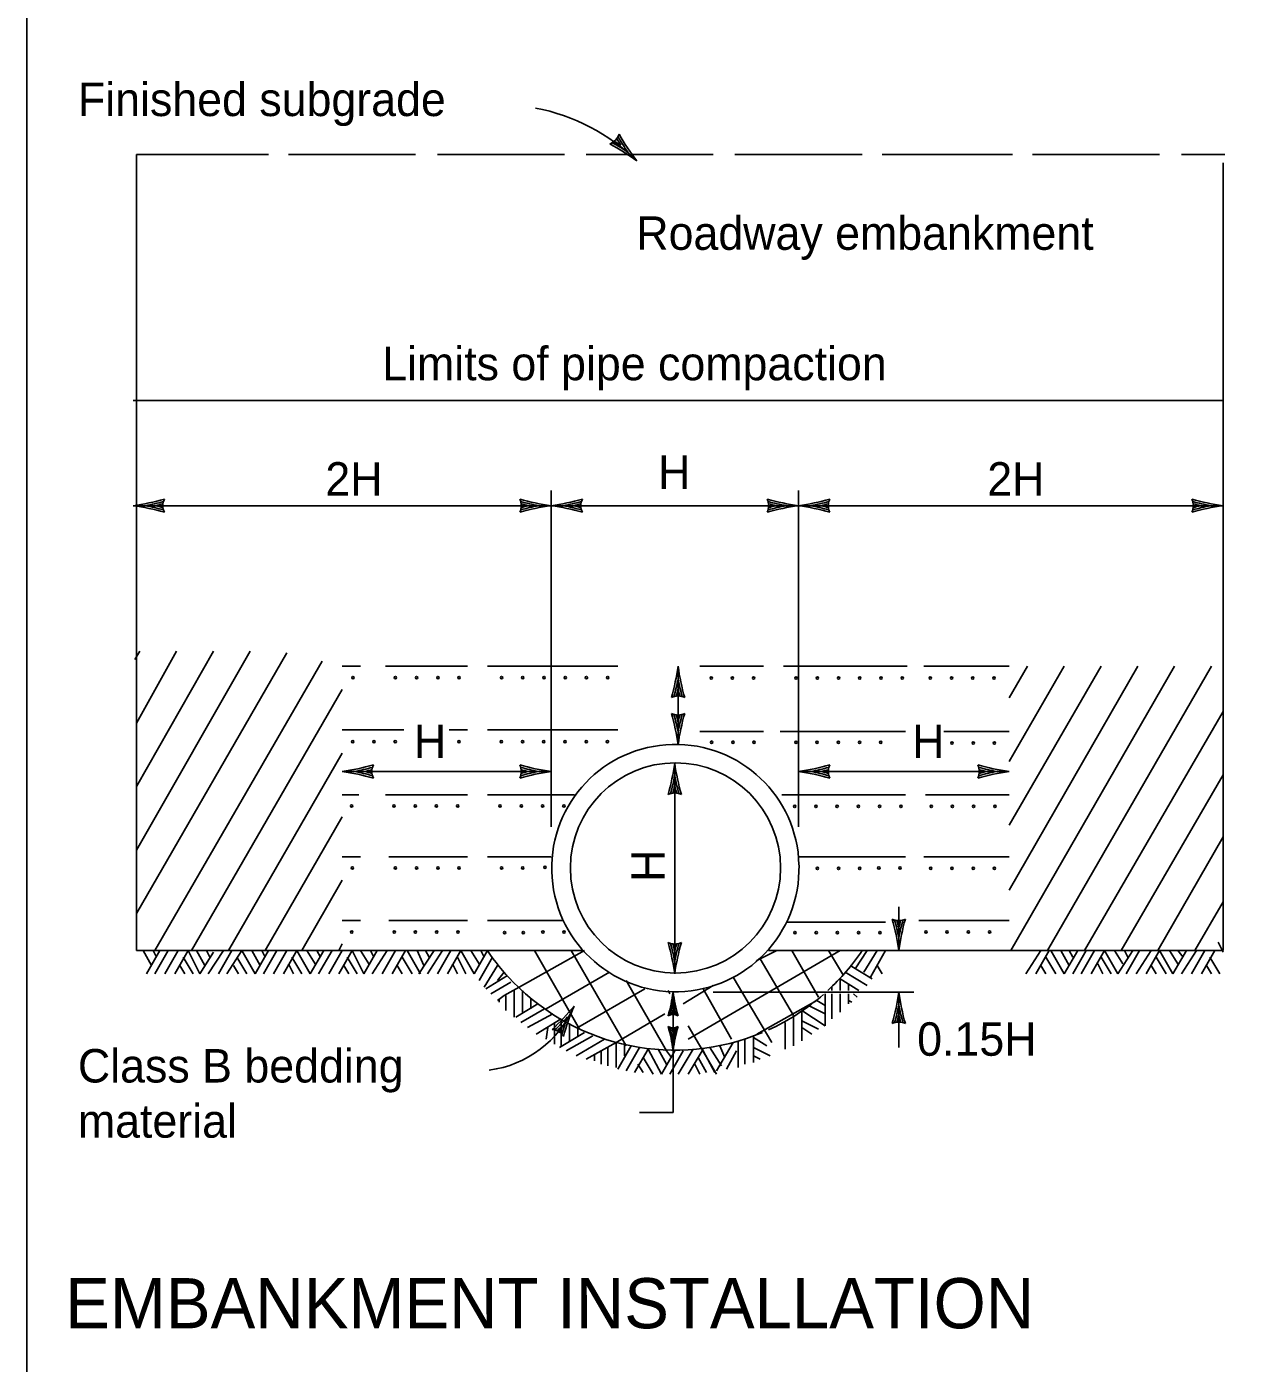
# Model space of a CAD drawing. Extents: x 0 to 390, y 0 to 265.
# Drawn here: x 0 to 73, y 105.1 to 185.1 of the extents above; entities that cross this region are included whole.
import ezdxf

# ---------------------------------------------------------------- set-up
doc = ezdxf.new("R2010")
doc.units = 0
doc.layers.add('D_Details', color=7, linetype='Continuous')
doc.layers.add('Default', color=7, linetype='Continuous')

msp = doc.modelspace()

# ---------------------------------------------------------------- linework, layer by layer
at = {"layer": 'D_Details'}
for p, q in [((6.562, 177.42), (14.462, 177.42)), ((6.562, 177.42), (6.562, 129.82)), ((15.662, 177.42), (23.262, 177.42)), ((24.562, 177.42), (32.162, 177.42)), ((33.462, 177.42), (41.062, 177.42)), ((42.362, 177.42), (49.962, 177.42)), ((51.162, 177.42), (58.962, 177.42)), ((60.162, 177.42), (67.762, 177.42)), ((69.062, 177.42), (71.662, 177.42)), ((71.562, 176.92), (71.562, 129.82)), ((6.362, 162.72), (71.562, 162.72)), ((31.362, 137.22), (31.362, 157.32)), ((46.162, 137.22), (46.162, 157.32)), ((6.362, 156.42), (31.362, 156.42)), ((31.362, 156.42), (46.162, 156.42)), ((46.162, 156.42), (71.562, 156.42)), ((6.462, 147.22), (6.762, 147.72)), ((6.562, 143.42), (8.962, 147.72)), ((6.562, 139.62), (11.162, 147.72)), ((6.562, 135.82), (13.362, 147.72)), ((6.562, 132.02), (15.562, 147.62)), ((7.662, 129.82), (17.662, 147.12)), ((18.862, 146.82), (19.962, 146.82)), ((21.462, 146.82), (26.362, 146.82)), ((27.562, 146.82), (35.362, 146.82)), ((38.962, 146.82), (38.962, 142.12)), ((40.262, 146.82), (44.062, 146.82)), ((45.262, 146.82), (52.662, 146.82)), ((53.662, 146.82), (58.762, 146.82)), ((58.762, 133.42), (66.462, 146.82)), ((58.762, 137.32), (64.262, 146.82)), ((58.762, 141.12), (62.062, 146.82)), ((58.762, 144.92), (59.862, 146.82)), ((58.862, 129.82), (68.662, 146.82)), ((61.062, 129.82), (70.862, 146.82)), ((9.862, 129.82), (18.862, 145.42)), ((63.262, 129.82), (71.562, 144.12)), ((18.862, 143.02), (22.562, 143.02)), ((25.262, 143.02), (26.362, 143.02)), ((27.562, 143.02), (35.362, 143.02)), ((40.262, 142.92), (44.062, 142.92)), ((45.062, 142.92), (52.562, 142.92)), ((54.862, 142.92), (58.762, 142.92)), ((12.062, 129.82), (18.862, 141.62)), ((38.762, 141.02), (38.762, 128.42)), ((18.862, 140.52), (31.362, 140.52)), ((46.162, 140.52), (58.762, 140.52)), ((65.462, 129.82), (71.562, 140.32)), ((18.862, 139.12), (19.862, 139.12)), ((21.462, 139.12), (26.362, 139.12)), ((27.562, 139.12), (32.762, 139.12)), ((45.162, 139.12), (52.562, 139.12)), ((53.762, 139.12), (58.762, 139.12)), ((14.262, 129.82), (18.862, 137.82)), ((67.662, 129.82), (71.562, 136.62)), ((18.862, 135.42), (19.962, 135.42)), ((21.662, 135.42), (26.362, 135.42)), ((27.562, 135.42), (31.362, 135.42)), ((46.162, 135.42), (52.562, 135.42)), ((53.662, 135.42), (58.762, 135.42)), ((16.462, 129.82), (18.862, 134.02)), ((69.862, 129.82), (71.562, 132.72)), ((52.162, 132.42), (52.162, 129.82)), ((18.862, 131.62), (19.962, 131.62)), ((21.662, 131.62), (26.362, 131.62)), ((27.562, 131.62), (32.062, 131.62)), ((45.462, 131.52), (51.362, 131.52)), ((53.362, 131.62), (58.762, 131.62)), ((71.562, 129.72), (71.262, 130.32)), ((6.562, 129.82), (27.562, 129.82)), ((7.462, 128.92), (6.962, 129.82)), ((7.162, 128.42), (7.962, 129.82)), ((7.762, 129.42), (7.562, 129.82)), ((7.662, 128.42), (8.462, 129.82)), ((8.262, 128.42), (9.062, 129.82)), ((8.862, 128.42), (9.662, 129.82)), ((10.362, 128.42), (9.662, 129.82)), ((10.662, 128.92), (10.162, 129.82)), ((10.362, 128.42), (11.162, 129.72)), ((10.962, 129.42), (10.762, 129.82)), ((10.862, 128.42), (11.762, 129.82)), ((11.162, 129.82), (11.162, 129.82)), ((11.462, 128.42), (12.262, 129.82)), ((11.962, 128.42), (12.862, 129.82)), ((13.662, 128.42), (12.862, 129.82)), ((13.962, 128.92), (13.462, 129.82)), ((13.662, 128.42), (14.462, 129.82)), ((14.262, 129.42), (14.062, 129.82)), ((14.162, 128.42), (14.962, 129.82)), ((14.762, 128.42), (15.562, 129.82)), ((15.362, 128.42), (16.162, 129.82)), ((16.962, 128.42), (16.162, 129.82)), ((17.262, 129.02), (16.762, 129.82)), ((16.962, 128.42), (17.762, 129.82)), ((17.562, 129.42), (17.362, 129.82)), ((17.462, 128.42), (18.262, 129.82)), ((18.062, 128.42), (18.862, 129.82)), ((18.662, 129.82), (18.862, 130.22)), ((18.662, 128.42), (19.462, 129.82)), ((20.162, 128.42), (19.462, 129.82)), ((20.462, 129.02), (19.962, 129.82)), ((20.162, 128.42), (20.962, 129.82)), ((20.762, 129.42), (20.562, 129.82)), ((20.662, 128.42), (21.562, 129.82)), ((20.962, 129.82), (20.962, 129.82)), ((21.262, 128.42), (22.062, 129.82)), ((21.862, 128.42), (22.662, 129.82)), ((23.562, 128.42), (22.762, 129.82)), ((23.762, 128.92), (23.362, 129.82)), ((23.462, 128.42), (24.362, 129.82)), ((24.062, 129.42), (23.862, 129.82)), ((23.962, 128.42), (24.862, 129.82)), ((24.562, 128.42), (25.362, 129.82)), ((25.162, 128.42), (25.962, 129.82)), ((26.762, 128.42), (25.962, 129.82)), ((27.062, 129.02), (26.562, 129.82)), ((26.762, 128.42), (27.562, 129.82)), ((27.362, 129.42), (27.162, 129.82)), ((27.562, 129.82), (33.262, 129.82)), ((29.462, 127.62), (33.362, 129.82)), ((30.362, 129.82), (33.062, 125.12)), ((32.562, 129.82), (35.862, 124.12)), ((39.562, 124.52), (48.662, 129.82)), ((43.662, 129.22), (44.862, 129.82)), ((44.362, 129.82), (49.962, 129.82)), ((45.762, 129.82), (47.362, 127.02)), ((47.962, 129.82), (48.862, 128.32)), ((49.562, 128.72), (50.262, 129.82)), ((49.662, 129.82), (49.662, 129.82)), ((49.962, 129.82), (71.562, 129.82)), ((50.062, 128.52), (50.862, 129.82)), ((50.462, 128.22), (51.362, 129.82)), ((59.462, 129.82), (59.462, 129.82)), ((59.762, 128.42), (60.662, 129.82)), ((60.362, 128.42), (61.162, 129.82)), ((62.062, 128.42), (61.262, 129.82)), ((62.362, 128.92), (61.862, 129.82)), ((62.062, 128.42), (62.862, 129.82)), ((62.562, 129.42), (62.362, 129.82)), ((62.562, 128.42), (63.362, 129.82)), ((63.062, 128.42), (63.862, 129.82)), ((63.662, 128.42), (64.462, 129.82)), ((65.262, 128.42), (64.462, 129.82)), ((65.562, 129.02), (65.062, 129.82)), ((65.262, 128.42), (66.162, 129.82)), ((65.862, 129.42), (65.662, 129.82)), ((65.762, 128.42), (66.562, 129.82)), ((66.362, 128.42), (67.262, 129.82)), ((66.962, 128.42), (67.762, 129.82)), ((68.562, 128.42), (67.762, 129.82)), ((68.862, 129.02), (68.362, 129.82)), ((68.562, 128.42), (69.362, 129.82)), ((69.162, 129.42), (68.862, 129.82)), ((69.062, 128.42), (69.962, 129.82)), ((69.362, 129.82), (69.362, 129.82)), ((69.662, 128.42), (70.462, 129.82)), ((70.262, 128.42), (71.062, 129.82)), ((9.462, 128.42), (9.162, 128.92)), ((9.962, 128.42), (9.362, 129.42)), ((12.662, 128.42), (12.362, 128.92)), ((13.162, 128.42), (12.562, 129.42)), ((15.962, 128.42), (15.662, 129.02)), ((16.462, 128.42), (15.862, 129.42)), ((19.262, 128.42), (18.962, 128.92)), ((19.762, 128.42), (19.162, 129.42)), ((22.462, 128.42), (22.162, 128.92)), ((23.062, 128.42), (22.462, 129.42)), ((25.762, 128.42), (25.462, 129.02)), ((26.262, 128.42), (25.762, 129.42)), ((27.062, 128.02), (27.862, 129.42)), ((27.362, 127.62), (28.162, 128.92)), ((43.862, 129.32), (45.862, 125.92)), ((50.562, 128.12), (49.262, 128.92)), ((51.162, 128.42), (50.862, 128.92)), ((60.962, 128.42), (60.662, 128.92)), ((61.562, 128.42), (60.962, 129.42)), ((64.362, 128.42), (64.062, 129.02)), ((64.862, 128.42), (64.262, 129.42)), ((67.562, 128.42), (67.262, 128.92)), ((68.162, 128.42), (67.562, 129.42)), ((68.662, 129.22), (68.662, 129.22)), ((70.862, 128.42), (70.562, 128.92)), ((71.362, 128.42), (70.762, 129.42)), ((27.462, 127.52), (28.762, 128.32)), ((27.662, 128.22), (27.662, 128.22)), ((27.762, 127.22), (28.962, 127.92)), ((28.162, 128.02), (28.562, 128.52)), ((31.062, 126.32), (34.862, 128.52)), ((35.862, 128.02), (38.262, 123.82)), ((42.262, 128.22), (44.562, 124.32)), ((48.662, 127.42), (48.662, 128.12)), ((49.762, 127.42), (48.662, 128.12)), ((50.262, 127.72), (48.962, 128.52)), ((28.162, 126.82), (28.562, 127.12)), ((28.562, 127.12), (29.462, 127.62)), ((28.662, 126.22), (28.662, 127.12)), ((29.162, 125.82), (29.162, 127.42)), ((29.662, 126.12), (29.662, 127.42)), ((32.962, 125.22), (36.962, 127.52)), ((38.362, 127.42), (38.462, 127.22)), ((38.662, 127.32), (38.662, 123.857)), ((39.262, 126.62), (41.062, 127.72)), ((40.462, 127.52), (42.162, 124.52)), ((41.062, 127.32), (53.062, 127.32)), ((47.762, 125.32), (47.762, 127.22)), ((48.162, 127.42), (48.162, 127.62)), ((48.162, 125.72), (48.162, 127.22)), ((48.662, 126.12), (48.662, 127.22)), ((49.162, 127.42), (49.162, 127.82)), ((49.162, 126.62), (49.162, 127.22)), ((49.662, 127.02), (49.462, 127.22)), ((52.162, 127.32), (52.162, 124.02)), ((28.262, 126.72), (28.262, 126.92)), ((29.262, 125.82), (30.562, 126.62)), ((29.562, 125.52), (30.962, 126.32)), ((30.162, 126.32), (30.162, 126.92)), ((43.662, 124.82), (47.262, 126.82)), ((47.762, 126.02), (46.762, 126.52)), ((47.762, 126.52), (47.262, 126.82)), ((49.362, 126.72), (49.162, 126.82)), ((29.962, 125.22), (31.462, 126.02)), ((30.462, 124.82), (31.962, 125.72)), ((31.562, 124.22), (31.562, 125.52)), ((31.962, 124.12), (31.962, 125.72)), ((35.262, 124.32), (38.162, 126.02)), ((45.362, 123.92), (45.362, 125.52)), ((45.862, 124.12), (45.862, 125.82)), ((46.362, 124.42), (46.362, 126.22)), ((47.762, 125.32), (46.362, 126.22)), ((47.362, 125.12), (46.362, 125.62)), ((31.062, 124.52), (31.162, 125.22)), ((31.862, 124.02), (33.362, 124.92)), ((32.262, 123.82), (33.862, 124.72)), ((32.462, 124.42), (32.462, 125.42)), ((32.962, 124.72), (32.962, 125.12)), ((39.562, 125.32), (41.262, 122.42)), ((43.462, 123.12), (43.462, 124.72)), ((46.962, 124.82), (46.362, 125.22)), ((32.862, 123.52), (34.562, 124.52)), ((33.462, 123.32), (35.262, 124.32)), ((34.762, 122.92), (34.762, 124.02)), ((35.262, 122.82), (35.262, 124.32)), ((35.362, 122.72), (36.162, 124.12)), ((35.762, 123.52), (35.762, 124.22)), ((35.862, 122.62), (36.662, 124.02)), ((36.362, 122.52), (37.162, 123.92)), ((37.962, 122.42), (37.162, 123.92)), ((38.262, 123.02), (37.762, 123.92)), ((38.962, 122.42), (39.862, 123.92)), ((39.562, 122.42), (40.462, 123.92)), ((41.562, 122.92), (40.862, 124.02)), ((41.262, 122.62), (42.262, 124.32)), ((41.762, 123.42), (41.462, 124.12)), ((42.562, 122.82), (42.562, 124.42)), ((42.962, 123.02), (42.962, 124.52)), ((44.262, 124.12), (43.462, 124.62)), ((44.462, 123.52), (43.462, 124.02)), ((33.962, 123.22), (33.962, 123.62)), ((34.362, 123.02), (34.362, 123.82)), ((35.462, 123.82), (35.462, 123.82)), ((37.462, 122.42), (36.862, 123.42)), ((37.962, 122.42), (38.762, 123.82)), ((38.562, 123.42), (38.262, 123.82)), ((38.462, 122.42), (39.262, 123.82)), ((38.662, 123.857), (38.662, 120.12)), ((40.662, 122.52), (40.162, 123.42)), ((41.162, 122.52), (40.462, 123.82)), ((41.862, 122.72), (42.462, 123.82)), ((42.062, 123.72), (42.062, 123.72)), ((43.862, 123.32), (43.462, 123.52)), ((36.862, 122.52), (36.562, 123.02)), ((40.262, 122.42), (39.962, 123.02)), ((38.662, 120.12), (36.662, 120.12))]:
    msp.add_line(p, q, dxfattribs=at)
for centre, radius in [((19.512, 146.14), 0.0707), ((22.052, 146.14), 0.0707), ((23.322, 146.14), 0.0707), ((24.592, 146.14), 0.0707), ((25.862, 146.14), 0.0707), ((28.402, 146.14), 0.0707), ((29.672, 146.14), 0.0707), ((30.942, 146.14), 0.0707), ((32.212, 146.14), 0.0707), ((33.482, 146.14), 0.0707), ((34.752, 146.14), 0.0707), ((40.94, 146.111), 0.0707), ((42.21, 146.111), 0.0707), ((43.48, 146.111), 0.0707), ((46.02, 146.111), 0.0707), ((47.29, 146.111), 0.0707), ((48.56, 146.111), 0.0707), ((49.83, 146.111), 0.0707), ((51.1, 146.111), 0.0707), ((52.37, 146.111), 0.0707), ((54.047, 146.109), 0.0707), ((55.317, 146.109), 0.0707), ((56.587, 146.109), 0.0707), ((57.857, 146.109), 0.0707), ((19.498, 142.302), 0.0707), ((20.768, 142.302), 0.0707), ((22.038, 142.302), 0.0707), ((25.848, 142.302), 0.0707), ((28.388, 142.302), 0.0707), ((29.658, 142.302), 0.0707), ((30.928, 142.302), 0.0707), ((32.198, 142.302), 0.0707), ((33.468, 142.302), 0.0707), ((34.738, 142.302), 0.0707), ((40.967, 142.276), 0.0707), ((42.237, 142.276), 0.0707), ((43.507, 142.276), 0.0707), ((46.006, 142.274), 0.0707), ((47.276, 142.274), 0.0707), ((48.546, 142.274), 0.0707), ((49.816, 142.274), 0.0707), ((51.086, 142.274), 0.0707), ((55.343, 142.221), 0.0707), ((56.613, 142.221), 0.0707), ((57.883, 142.221), 0.0707), ((38.804, 134.755), 6.287), ((19.427, 138.464), 0.0707), ((21.967, 138.464), 0.0707), ((23.237, 138.464), 0.0707), ((24.507, 138.464), 0.0707), ((25.777, 138.464), 0.0707), ((28.317, 138.464), 0.0707), ((29.587, 138.464), 0.0707), ((30.857, 138.464), 0.0707), ((32.127, 138.464), 0.0707), ((45.935, 138.436), 0.0707), ((47.205, 138.436), 0.0707), ((48.475, 138.436), 0.0707), ((49.745, 138.436), 0.0707), ((51.015, 138.436), 0.0707), ((52.285, 138.436), 0.0707), ((54.1, 138.438), 0.0707), ((55.37, 138.438), 0.0707), ((56.64, 138.438), 0.0707), ((57.91, 138.438), 0.0707), ((19.479, 134.753), 0.0707), ((22.052, 134.753), 0.0707), ((23.322, 134.753), 0.0707), ((24.592, 134.753), 0.0707), ((25.862, 134.753), 0.0707), ((28.402, 134.753), 0.0707), ((29.672, 134.753), 0.0707), ((30.993, 134.796), 0.0707), ((47.29, 134.725), 0.0707), ((48.56, 134.725), 0.0707), ((49.83, 134.725), 0.0707), ((50.968, 134.751), 0.0707), ((52.237, 134.751), 0.0707), ((54.073, 134.735), 0.0707), ((55.343, 134.735), 0.0707), ((56.613, 134.735), 0.0707), ((57.883, 134.735), 0.0707), ((19.441, 130.915), 0.0707), ((21.981, 130.915), 0.0707), ((23.251, 130.915), 0.0707), ((24.521, 130.915), 0.0707), ((25.791, 130.915), 0.0707), ((28.584, 130.886), 0.0707), ((29.698, 130.886), 0.0707), ((30.871, 130.915), 0.0707), ((32.141, 130.915), 0.0707), ((45.95, 130.887), 0.0707), ((47.22, 130.887), 0.0707), ((48.49, 130.887), 0.0707), ((49.76, 130.887), 0.0707), ((51.03, 130.887), 0.0707), ((53.782, 130.927), 0.0707), ((55.052, 130.927), 0.0707), ((56.322, 130.927), 0.0707), ((57.592, 130.927), 0.0707)]:
    msp.add_circle(centre, radius, dxfattribs=at)
for centre, radius, start, end in [((28.211, 168.552), 11.858, 45.69631, 79.19864), ((34.594, 178.893), 0.874, 288.91131, 342.4813), ((47.621, 185.637), 14.313, 210.52539, 212.33694), ((47.621, 185.637), 14.188, 210.26623, 214.69531), ((47.621, 185.637), 14.063, 209.88284, 217.69631), ((28.168, 165.705), 14.063, 53.69631, 61.50799), ((28.168, 165.705), 14.188, 56.6973, 61.12639), ((28.168, 165.705), 14.313, 59.05568, 60.86723), ((4.404, 170.346), 14.063, 278, 285.81169), ((9.016, 156.42), 0.874, 153.215, 206.78499), ((33.318, 170.346), 14.063, 254.18653, 262), ((28.706, 156.42), 0.874, 333.215, 26.78499), ((29.404, 170.346), 14.063, 278, 285.81169), ((34.016, 156.42), 0.874, 153.215, 206.78499), ((48.118, 170.346), 14.063, 254.18653, 262), ((43.506, 156.42), 0.874, 333.215, 26.78499), ((44.204, 170.346), 14.063, 278, 285.81169), ((48.816, 156.42), 0.874, 153.215, 206.78499), ((73.518, 170.346), 14.063, 254.18653, 262), ((68.906, 156.42), 0.874, 333.215, 26.78499), ((4.404, 142.494), 14.063, 74.18653, 82), ((4.404, 170.346), 14.188, 281.00099, 285.43008), ((4.404, 142.494), 14.188, 74.56992, 78.99901), ((4.404, 170.346), 14.313, 283.35937, 285.17092), ((4.404, 142.494), 14.313, 74.82908, 76.64064), ((33.318, 142.494), 14.063, 98, 105.81169), ((33.318, 170.346), 14.188, 254.56992, 258.99901), ((33.318, 142.494), 14.188, 101.00099, 105.43008), ((33.318, 170.346), 14.313, 254.82908, 256.64064), ((33.318, 142.494), 14.313, 103.35937, 105.17092), ((29.404, 142.494), 14.063, 74.18653, 82), ((29.404, 170.346), 14.188, 281.00099, 285.43008), ((29.404, 142.494), 14.188, 74.56992, 78.99901), ((29.404, 170.346), 14.313, 283.35937, 285.17092), ((29.404, 142.494), 14.313, 74.82908, 76.64064), ((48.118, 142.494), 14.063, 98, 105.81169), ((48.118, 170.346), 14.188, 254.56992, 258.99901), ((48.118, 142.494), 14.188, 101.00099, 105.43008), ((48.118, 170.346), 14.313, 254.82908, 256.64064), ((48.118, 142.494), 14.313, 103.35937, 105.17092), ((44.204, 142.494), 14.063, 74.18653, 82), ((44.204, 170.346), 14.188, 281.00099, 285.43008), ((44.204, 142.494), 14.188, 74.56992, 78.99901), ((44.204, 170.346), 14.313, 283.35937, 285.17092), ((44.204, 142.494), 14.313, 74.82908, 76.64064), ((73.518, 142.494), 14.063, 98, 105.81169), ((73.518, 170.346), 14.188, 254.56992, 258.99901), ((73.518, 142.494), 14.188, 101.00099, 105.43008), ((73.518, 170.346), 14.313, 254.82908, 256.64064), ((73.518, 142.494), 14.313, 103.35937, 105.17092), ((25.035, 148.777), 14.063, 344.18653, 352), ((52.886, 148.777), 14.063, 188, 195.81169), ((25.035, 148.777), 14.188, 344.56992, 348.99901), ((52.886, 148.777), 14.188, 191.00099, 195.43008), ((38.961, 144.165), 0.874, 63.215, 116.78499), ((25.035, 148.777), 14.313, 344.82908, 346.64064), ((52.886, 148.777), 14.313, 193.35937, 195.17092), ((25.035, 140.163), 14.063, 8, 15.81169), ((38.961, 144.775), 0.874, 243.215, 296.78499), ((25.035, 140.163), 14.188, 11.00099, 15.43008), ((25.035, 140.163), 14.313, 13.35937, 15.17092), ((52.886, 140.163), 14.188, 164.56992, 168.99901), ((52.886, 140.163), 14.063, 164.18653, 172), ((52.886, 140.163), 14.313, 164.82908, 166.64064), ((38.798, 134.747), 7.397, 1.52094, 1.35499), ((16.904, 154.446), 14.063, 278, 285.81169), ((16.904, 154.446), 14.188, 281.00099, 285.43008), ((21.516, 140.52), 0.874, 153.215, 206.78499), ((33.318, 154.446), 14.063, 254.18653, 262), ((28.706, 140.52), 0.874, 333.215, 26.78499), ((33.318, 154.446), 14.188, 254.56992, 258.99901), ((24.835, 142.977), 14.063, 344.18653, 352), ((52.686, 142.977), 14.063, 188, 195.81169), ((44.204, 154.446), 14.063, 278, 285.81169), ((44.204, 154.446), 14.188, 281.00099, 285.43008), ((48.816, 140.52), 0.874, 153.215, 206.78499), ((60.718, 154.446), 14.063, 254.18653, 262), ((56.106, 140.52), 0.874, 333.215, 26.78499), ((60.718, 154.446), 14.188, 254.56992, 258.99901), ((16.904, 126.594), 14.063, 74.18653, 82), ((16.904, 126.594), 14.188, 74.56992, 78.99901), ((16.904, 154.446), 14.313, 283.35937, 285.17092), ((16.904, 126.594), 14.313, 74.82908, 76.64064), ((33.318, 126.594), 14.063, 98, 105.81169), ((33.318, 126.594), 14.188, 101.00099, 105.43008), ((33.318, 154.446), 14.313, 254.82908, 256.64064), ((33.318, 126.594), 14.313, 103.35937, 105.17092), ((24.835, 142.977), 14.188, 344.56992, 348.99901), ((52.686, 142.977), 14.188, 191.00099, 195.43008), ((44.204, 126.594), 14.063, 74.18653, 82), ((44.204, 126.594), 14.188, 74.56992, 78.99901), ((44.204, 154.446), 14.313, 283.35937, 285.17092), ((44.204, 126.594), 14.313, 74.82908, 76.64064), ((60.718, 126.594), 14.063, 98, 105.81169), ((60.718, 126.594), 14.188, 101.00099, 105.43008), ((60.718, 154.446), 14.313, 254.82908, 256.64064), ((60.718, 126.594), 14.313, 103.35937, 105.17092), ((38.761, 138.365), 0.874, 63.215, 116.78499), ((24.835, 142.977), 14.313, 344.82908, 346.64064), ((52.686, 142.977), 14.313, 193.35937, 195.17092), ((38.235, 127.863), 14.063, 8, 15.81169), ((52.161, 132.475), 0.874, 243.215, 296.78499), ((38.235, 127.863), 14.188, 11.00099, 15.43008), ((38.235, 127.863), 14.313, 13.35937, 15.17092), ((66.086, 127.863), 14.188, 164.56992, 168.99901), ((66.086, 127.863), 14.063, 164.18653, 172), ((66.086, 127.863), 14.313, 164.82908, 166.64064), ((24.835, 126.463), 14.063, 8, 15.81169), ((38.761, 131.075), 0.874, 243.215, 296.78499), ((52.686, 126.463), 14.063, 164.18653, 172), ((38.765, 137.383), 13.526, 213.86279, 224.28004), ((24.835, 126.463), 14.188, 11.00099, 15.43008), ((24.835, 126.463), 14.313, 13.35937, 15.17092), ((52.686, 126.463), 14.188, 164.56992, 168.99901), ((52.686, 126.463), 14.313, 164.82908, 166.64064), ((38.765, 137.383), 13.526, 312.5904, 325.97997), ((38.765, 137.383), 13.526, 224.28004, 292.84251), ((28.217, 128.788), 10.547, 344.18653, 352), ((49.105, 128.788), 10.547, 188, 195.81169), ((38.765, 137.383), 13.526, 294.42818, 311.11588), ((38.235, 129.277), 14.063, 344.18653, 352), ((66.086, 129.277), 14.063, 188, 195.81169), ((26.841, 129.031), 6.419, 277.38287, 336.69876), ((21.833, 135.372), 14.063, 313.02429, 320.83776), ((45.666, 120.96), 14.063, 156.83776, 164.64944), ((28.217, 128.788), 10.641, 344.56992, 348.99901), ((28.217, 128.788), 10.734, 344.82908, 346.64064), ((49.105, 128.788), 10.641, 191.00099, 195.43008), ((49.105, 128.788), 10.734, 193.35937, 195.17092), ((38.235, 129.277), 14.188, 344.56992, 348.99901), ((66.086, 129.277), 14.188, 191.00099, 195.43008), ((21.833, 135.372), 14.188, 313.40768, 317.83676), ((45.666, 120.96), 14.188, 159.83875, 164.26784), ((38.661, 125.329), 0.655, 63.215, 116.78499), ((52.161, 124.665), 0.874, 63.215, 116.78499), ((38.235, 129.277), 14.313, 344.82908, 346.64064), ((66.086, 129.277), 14.313, 193.35937, 195.17092), ((31.363, 124.22), 0.874, 32.05276, 85.62275), ((21.833, 135.372), 14.313, 313.66684, 315.47839), ((45.666, 120.96), 14.313, 162.19713, 164.00868), ((28.217, 122.389), 10.547, 8, 15.81169), ((38.661, 125.848), 0.655, 243.215, 296.78499), ((28.217, 122.389), 10.641, 11.00099, 15.43008), ((28.217, 122.389), 10.734, 13.35937, 15.17092), ((49.105, 122.389), 10.641, 164.56992, 168.99901), ((49.105, 122.389), 10.547, 164.18653, 172), ((49.105, 122.389), 10.734, 164.82908, 166.64064)]:
    msp.add_arc(centre, radius, start, end, dxfattribs=at)
at = {"layer": 'Default'}
for points in [[(0, 265), (326.25, 265), (326.25, 255), (390, 255), (390, 37.5), (315, 37.5), (315, 0), (0, 0)], [(0, 262.5), (326.25, 262.5), (326.25, 252.5), (390, 252.5), (390, 40), (315, 40), (315, 2.5), (0, 2.5)]]:
    msp.add_lwpolyline(points, close=True, dxfattribs=at)

# ---------------------------------------------------------------- texts
at = {"layer": 'D_Details'}
for s, height, p in [('Finished subgrade', 2, (3.062, 179.722)), ('Roadway embankment', 2, (36.462, 171.722)), ('Limits of pipe compaction', 2, (21.262, 163.922)), ('H', 2, (37.762, 157.422)), ('2H', 2, (17.862, 157.022)), ('2H', 2, (57.454, 157.022)), ('H', 2, (23.162, 141.322)), ('H', 2, (52.962, 141.322)), ('0.15H', 2, (53.262, 123.522)), ('Class B bedding', 2, (3.062, 121.922)), ('material', 2, (3.062, 118.622)), ('EMBANKMENT INSTALLATION', 3, (2.304, 107.222))]:
    msp.add_text(s, height=height, dxfattribs=at).set_placement(p)
msp.add_text('H', height=2, rotation=90, dxfattribs=at).set_placement((38.162, 133.922))

doc.saveas('drawing.dxf')
